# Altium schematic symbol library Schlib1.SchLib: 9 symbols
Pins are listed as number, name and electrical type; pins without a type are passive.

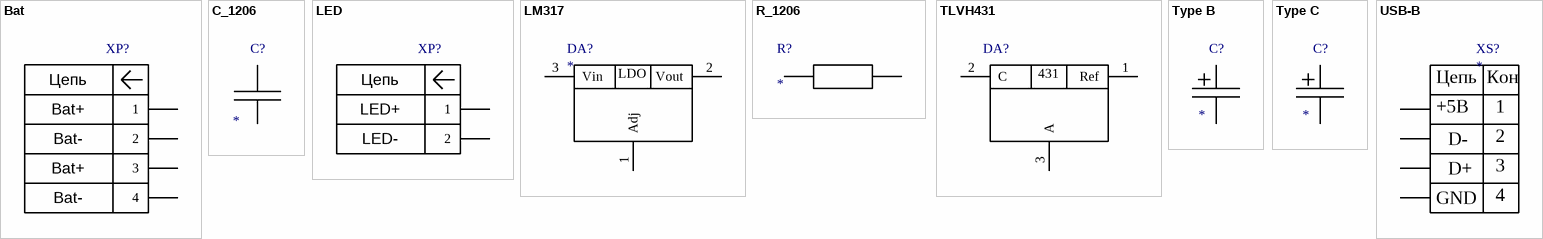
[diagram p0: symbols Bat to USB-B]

## Bat
designator XP?  (value not drawn)
footprint PLS-4
pins: 1, 2, 3, 4

## C_1206
designator C?
footprint RC_1206
pins: 1, 2

## LED
designator XP?  (value not drawn)
footprint PLS-2
pins: 1, 2

## LM317
designator DA?
footprint SOT-223
pins: 1 Adj, 2 Vout, 3 Vin

## R_1206
designator R?
footprint RC_1206
pins: 1, 2

## TLVH431
designator DA?  (value not drawn)
footprint SOT-23
pins: 1 Ref, 2 C, 3 A

## Type B
designator C?
footprint Type B
pins: 1, 2

## Type C
designator C?
footprint Type C
pins: 1, 2

## USB-B
designator XS?
footprint USB-B
pins: 1, 2, 3, 4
